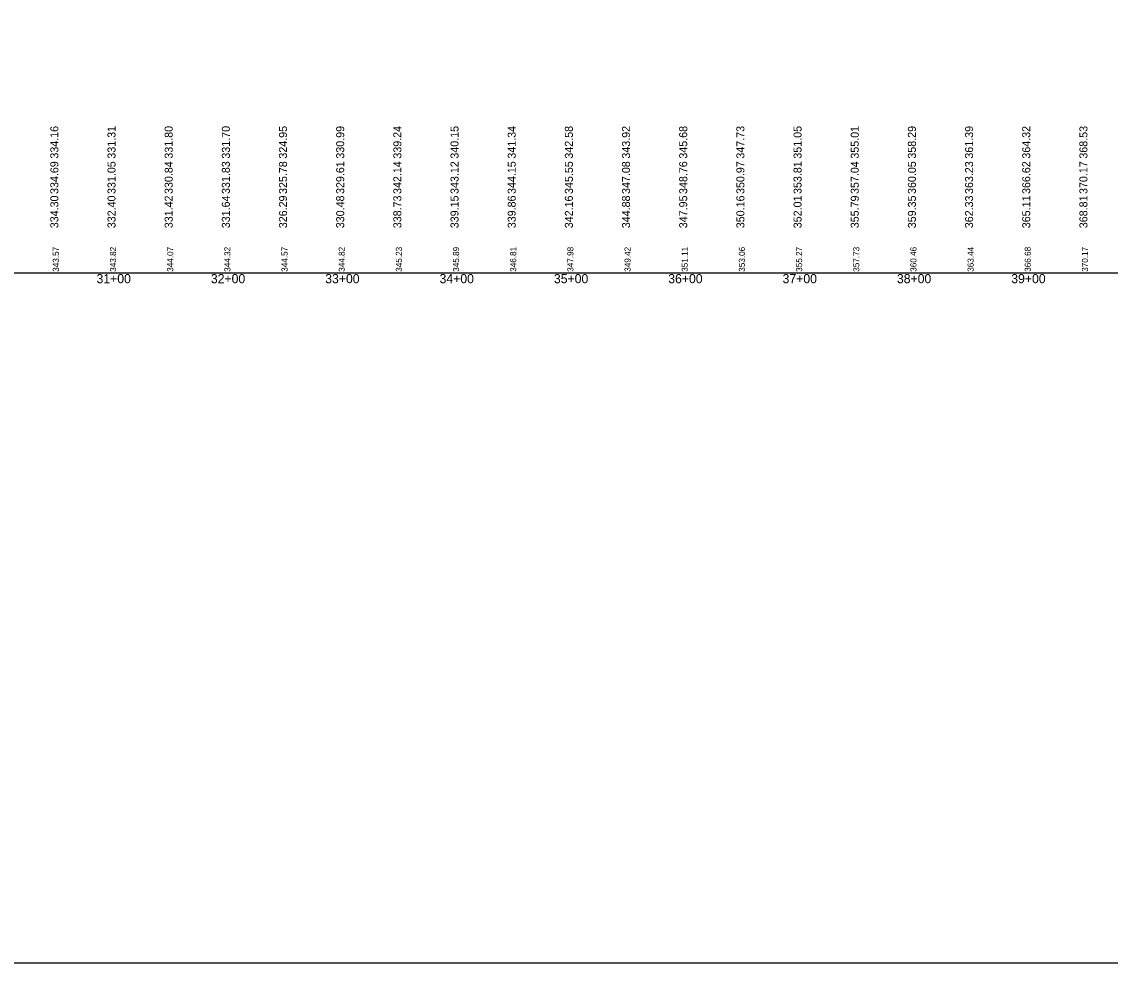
# Model space of a CAD drawing. Extents: x 2005261 to 2010661, y 1001568 to 1006764.
# Drawn here: x 2007639 to 2008591, y 1003464 to 1004288 of the extents above; entities that cross this region are included whole.
import ezdxf

# ---------------------------------------------------------------- set-up
doc = ezdxf.new("R2010")
doc.units = 0
for name, color, linetype in [('RD_DDB_StaTX', 7, 'Continuous'), ('RD_DDB_StripGrade', 7, 'Continuous'), ('RD_GPK_Profile_Cell', 7, 'Continuous'), ('RD_Sketch2', 7, 'Continuous'), ('RD_Sketch3', 7, 'Continuous'), ('RD_Sketch4', 7, 'Continuous')]:
    doc.layers.add(name, color=color, linetype=linetype)

msp = doc.modelspace()

# ---------------------------------------------------------------- linework, layer by layer
at = {"layer": 'RD_GPK_Profile_Cell'}
msp.add_line((2006171.73, 1004068.4), (2009471.73, 1004068.4), dxfattribs=at)
at = {"layer": 'RD_Sketch4'}
msp.add_lwpolyline([(2005261.48, 1006764.34), (2010661.48, 1006764.34), (2010661.48, 1003464.34), (2005261.48, 1003464.34)], close=True, dxfattribs=at)

# ---------------------------------------------------------------- texts
at = {"layer": 'RD_DDB_StaTX'}
for s, p in [('31+00', (2007704.14, 1004059.4)), ('32+00', (2007804.14, 1004059.4)), ('33+00', (2007904.14, 1004059.4)), ('34+00', (2008004.14, 1004059.4)), ('35+00', (2008104.14, 1004059.4)), ('36+00', (2008204.14, 1004059.4)), ('37+00', (2008304.14, 1004059.4)), ('38+00', (2008404.14, 1004059.4)), ('39+00', (2008504.14, 1004059.4))]:
    msp.add_text(s, height=8, dxfattribs=at).set_placement(p)
at = {"layer": 'RD_DDB_StripGrade'}
for s, height, p in [('334.69', 7, (2007670.73, 1004137.48)), ('331.05', 7, (2007720.73, 1004137.48)), ('330.84', 7, (2007770.73, 1004137.48)), ('331.83', 7, (2007820.73, 1004137.48)), ('325.78', 7, (2007870.73, 1004137.48)), ('329.61', 7, (2007920.73, 1004137.48)), ('342.14', 7, (2007970.73, 1004137.48)), ('343.12', 7, (2008020.73, 1004137.48)), ('344.15', 7, (2008070.73, 1004137.48)), ('345.55', 7, (2008120.73, 1004137.48)), ('347.08', 7, (2008170.73, 1004137.48)), ('348.76', 7, (2008220.73, 1004137.48)), ('350.97', 7, (2008270.73, 1004137.48)), ('353.81', 7, (2008320.73, 1004137.48)), ('357.04', 7, (2008370.73, 1004137.48)), ('360.05', 7, (2008420.73, 1004137.48)), ('363.23', 7, (2008470.73, 1004137.48)), ('366.62', 7, (2008520.73, 1004137.48)), ('370.17', 7, (2008570.73, 1004137.48)), ('343.57', 5.331, (2007671.23, 1004069.4)), ('343.82', 5.331, (2007721.23, 1004069.4)), ('344.07', 5.331, (2007771.23, 1004069.4)), ('344.32', 5.331, (2007821.23, 1004069.4)), ('344.57', 5.331, (2007871.23, 1004069.4)), ('344.82', 5.331, (2007921.23, 1004069.4)), ('345.23', 5.331, (2007971.23, 1004069.4)), ('345.89', 5.331, (2008021.23, 1004069.4)), ('346.81', 5.331, (2008071.23, 1004069.4)), ('347.98', 5.331, (2008121.23, 1004069.4)), ('349.42', 5.331, (2008171.23, 1004069.4)), ('351.11', 5.331, (2008221.23, 1004069.4)), ('353.06', 5.331, (2008271.23, 1004069.4)), ('355.27', 5.331, (2008321.23, 1004069.4)), ('357.73', 5.331, (2008371.23, 1004069.4)), ('360.46', 5.331, (2008421.23, 1004069.4)), ('363.44', 5.331, (2008471.23, 1004069.4)), ('366.68', 5.331, (2008521.23, 1004069.4)), ('370.17', 5.331, (2008571.23, 1004069.4))]:
    msp.add_text(s, height=height, rotation=90, dxfattribs=at).set_placement(p)
at = {"layer": 'RD_Sketch2'}
for s, p in [('334.30', (2007670.73, 1004107.51)), ('332.40', (2007720.73, 1004107.51)), ('331.42', (2007770.73, 1004107.51)), ('331.64', (2007820.73, 1004107.51)), ('326.29', (2007870.73, 1004107.51)), ('330.48', (2007920.73, 1004107.51)), ('338.73', (2007970.73, 1004107.51)), ('339.15', (2008020.73, 1004107.51)), ('339.86', (2008070.73, 1004107.51)), ('342.16', (2008120.73, 1004107.51)), ('344.88', (2008170.73, 1004107.51)), ('347.95', (2008220.73, 1004107.51)), ('350.16', (2008270.73, 1004107.51)), ('352.01', (2008320.73, 1004107.51)), ('355.79', (2008370.73, 1004107.51)), ('359.35', (2008420.73, 1004107.51)), ('362.33', (2008470.73, 1004107.51)), ('365.11', (2008520.73, 1004107.51)), ('368.81', (2008570.73, 1004107.51))]:
    msp.add_text(s, height=7, rotation=90, dxfattribs=at).set_placement(p)
at = {"layer": 'RD_Sketch3'}
for s, p in [('334.16', (2007670.73, 1004168.4)), ('331.31', (2007720.73, 1004168.4)), ('331.80', (2007770.73, 1004168.4)), ('331.70', (2007820.73, 1004168.4)), ('324.95', (2007870.73, 1004168.4)), ('330.99', (2007920.73, 1004168.4)), ('339.24', (2007970.73, 1004168.4)), ('340.15', (2008020.73, 1004168.4)), ('341.34', (2008070.73, 1004168.4)), ('342.58', (2008120.73, 1004168.4)), ('343.92', (2008170.73, 1004168.4)), ('345.68', (2008220.73, 1004168.4)), ('347.73', (2008270.73, 1004168.4)), ('351.05', (2008320.73, 1004168.4)), ('355.01', (2008370.73, 1004168.4)), ('358.29', (2008420.73, 1004168.4)), ('361.39', (2008470.73, 1004168.4)), ('364.32', (2008520.73, 1004168.4)), ('368.53', (2008570.73, 1004168.4))]:
    msp.add_text(s, height=7, rotation=90, dxfattribs=at).set_placement(p)

doc.saveas('drawing.dxf')
